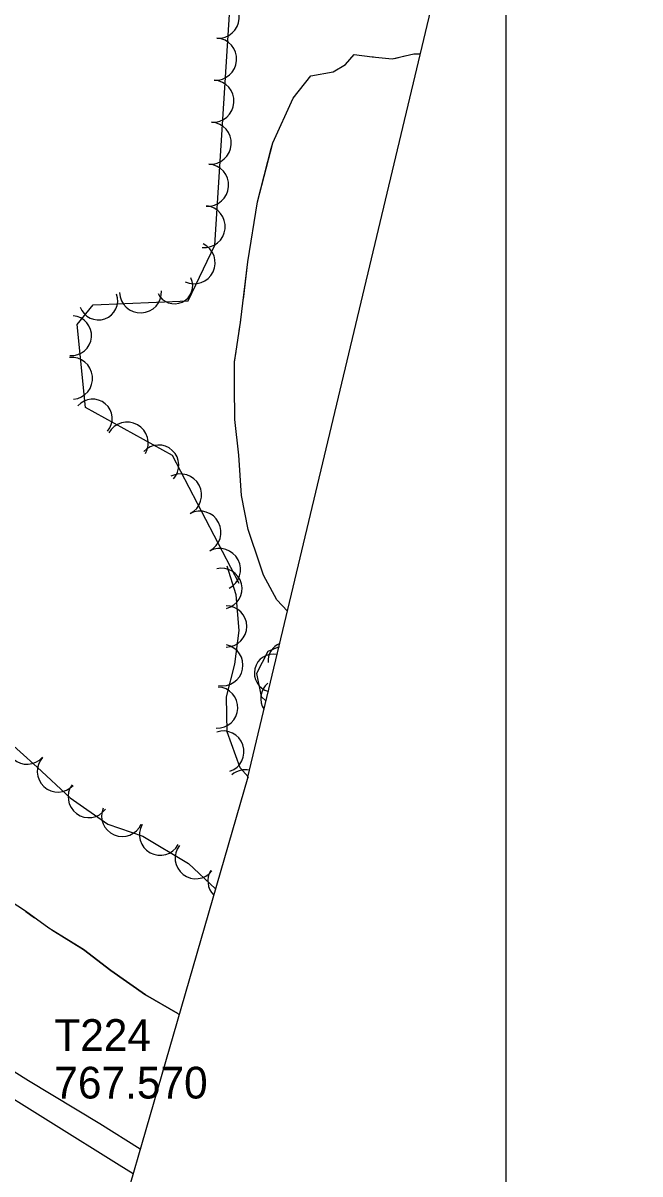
# Model space of a CAD drawing. Extents: x 591954 to 597000, y 198576 to 213500.
# Drawn here: x 596408.6 to 596525.3, y 204070.5 to 204288.1 of the extents above; entities that cross this region are included whole.
import ezdxf

# ---------------------------------------------------------------- set-up
doc = ezdxf.new("R2010")
doc.units = 0
for name, color, linetype in [('Level 10', 7, 'Continuous'), ('Level 11', 7, 'Continuous'), ('Level 18', 7, 'Continuous'), ('Level 19', 7, 'Continuous'), ('Level 4', 7, 'Continuous'), ('Level 5', 7, 'Continuous')]:
    doc.layers.add(name, color=color, linetype=linetype)

msp = doc.modelspace()

# ---------------------------------------------------------------- linework, layer by layer
at = {"layer": 'Level 10'}
for p, q in [((596500, 204000), (596500, 205500)), ((596500, 204000), (596500, 205500)), ((596500, 204000), (596500, 205500)), ((596500, 203500), (596500, 204500))]:
    msp.add_line(p, q, dxfattribs=at)
at = {"layer": 'Level 11'}
for points in [[(596429.44, 204070.52), (596426.81, 204072.19), (596413.87, 204080.23), (596400.87, 204088.31), (596389, 204095.58), (596377.25, 204102.78), (596364.91, 204110.13), (596352.62, 204117.51), (596341.53, 204124.08), (596329.34, 204131.2), (596316.86, 204138.42), (596305.16, 204145.16), (596290.94, 204153.27), (596277.68, 204160.85), (596266.03, 204167.49), (596254.43, 204174.01), (596246.04, 204178.87)], [(596430.78, 204075.17), (596423.12, 204079.95), (596409.67, 204088.08), (596395.51, 204096.91), (596377.37, 204107.84), (596359.1, 204118.92), (596339.87, 204130.04), (596322.37, 204140.72), (596307.82, 204149.24)]]:
    msp.add_lwpolyline(points, dxfattribs=at)
at = {"layer": 'Level 18'}
for points in [[(596449.49, 204182.14), (596436.86, 204206.32), (596420.41, 204215.43), (596418.86, 204231.12), (596421.86, 204234.86), (596439.83, 204235.58), (596444.88, 204246.14), (596448.48, 204302.69), (596477.13, 204303.31), (596488.73, 204303.07)], [(596449.49, 204182.14), (596436.86, 204206.32), (596420.41, 204215.43), (596418.86, 204231.12), (596421.86, 204234.86), (596439.83, 204235.58), (596444.88, 204246.14), (596448.48, 204302.69), (596477.13, 204303.31), (596488.73, 204303.07)], [(596449.49, 204182.14), (596436.86, 204206.32), (596420.41, 204215.43), (596418.86, 204231.12), (596421.86, 204234.86), (596439.83, 204235.58), (596444.88, 204246.14), (596448.48, 204302.69), (596477.13, 204303.31), (596488.73, 204303.07)], [(596451.16, 204145.58), (596449.68, 204147.31), (596447.19, 204154.08), (596447.1, 204160.73), (596448.68, 204166.91), (596449.45, 204173.29), (596448.88, 204180.01), (596447.2, 204185.4)], [(596349.72, 204182.23), (596354.79, 204180.08), (596364.73, 204175.11), (596375.76, 204169.42), (596387.49, 204163.2), (596396.9, 204157.48), (596404.83, 204153.22), (596411.29, 204147.43), (596417.54, 204141.65), (596424.63, 204136.66), (596431.29, 204134.37), (596439.92, 204129.2), (596445.03, 204124.39)], [(596457.03, 204170.2), (596454.91, 204169.28), (596452.78, 204165.11), (596453.65, 204160.77), (596454.57, 204159.87)], [(596451.24, 204145.49), (596451.23, 204145.5)]]:
    msp.add_lwpolyline(points, dxfattribs=at)
for centre, radius, start, end in [((596445.53, 204289.23), 3.98, 266.3698, 86.3545), ((596445.53, 204289.23), 3.98, 266.3698, 86.3545), ((596445.53, 204289.23), 3.98, 266.3698, 86.3545), ((596445.03, 204281.29), 3.98, 266.3703, 86.3549), ((596445.03, 204281.29), 3.98, 266.3703, 86.3549), ((596445.03, 204281.29), 3.98, 266.3703, 86.3549), ((596444.52, 204273.34), 3.98, 266.3626, 86.3473), ((596444.52, 204273.34), 3.98, 266.3626, 86.3473), ((596444.52, 204273.34), 3.98, 266.3626, 86.3473), ((596444.02, 204265.4), 3.98, 266.3703, 86.3549), ((596444.02, 204265.4), 3.98, 266.3703, 86.3549), ((596444.02, 204265.4), 3.98, 266.3703, 86.3549), ((596443.51, 204257.46), 3.98, 266.3698, 86.3545), ((596443.51, 204257.46), 3.98, 266.3698, 86.3545), ((596443.51, 204257.46), 3.98, 266.3698, 86.3545), ((596442.89, 204249.62), 3.96, 264.3864, 84.3711), ((596442.89, 204249.62), 3.96, 264.3864, 84.3711), ((596442.89, 204249.62), 3.96, 264.3864, 84.3711), ((596440.97, 204242.79), 3.98, 244.4567, 64.4414), ((596440.97, 204242.79), 3.98, 244.4567, 64.4414), ((596440.97, 204242.79), 3.98, 244.4567, 64.4414), ((596437.25, 204238.47), 3.44, 205.0698, 25.0545), ((596437.25, 204238.47), 3.44, 205.0698, 25.0545), ((596437.25, 204238.47), 3.44, 205.0698, 25.0545), ((596422.86, 204235.64), 3.65, 199.6018, 19.5865), ((596422.86, 204235.64), 3.65, 199.6018, 19.5865), ((596422.86, 204235.64), 3.65, 199.6018, 19.5865), ((596430.83, 204237.3), 3.98, 182.283, 2.2677), ((596430.83, 204237.3), 3.98, 182.283, 2.2677), ((596430.83, 204237.3), 3.98, 182.283, 2.2677), ((596417.79, 204229.02), 3.77, 265.4013, 85.386), ((596417.79, 204229.02), 3.77, 265.4013, 85.386), ((596417.79, 204229.02), 3.77, 265.4013, 85.386), ((596417.77, 204220.94), 3.98, 275.638, 95.6227), ((596417.77, 204220.94), 3.98, 275.638, 95.6227), ((596417.77, 204220.94), 3.98, 275.638, 95.6227), ((596421.79, 204213.34), 3.67, 319.6577, 139.6424), ((596421.79, 204213.34), 3.67, 319.6577, 139.6424), ((596421.79, 204213.34), 3.67, 319.6577, 139.6424), ((596428.31, 204208.68), 3.98, 331.0244, 151.009), ((596428.31, 204208.68), 3.98, 331.0244, 151.009), ((596428.31, 204208.68), 3.98, 331.0244, 151.009), ((596434.24, 204204.51), 3.82, 317.1901, 137.1747), ((596434.24, 204204.51), 3.82, 317.1901, 137.1747), ((596434.24, 204204.51), 3.82, 317.1901, 137.1747), ((596438.39, 204198.89), 3.98, 297.5707, 117.5554), ((596438.39, 204198.89), 3.98, 297.5707, 117.5554), ((596438.39, 204198.89), 3.98, 297.5707, 117.5554), ((596442.07, 204191.84), 3.98, 297.5771, 117.5618), ((596442.07, 204191.84), 3.98, 297.5771, 117.5618), ((596442.07, 204191.84), 3.98, 297.5771, 117.5618), ((596445.76, 204184.78), 3.98, 297.5674, 117.5521), ((596445.76, 204184.78), 3.98, 297.5674, 117.5521), ((596445.76, 204184.78), 3.98, 297.5674, 117.5521), ((596446.17, 204181.18), 3.85, 283.9934, 103.9781), ((596447.03, 204174.03), 3.89, 270.1107, 90.0954), ((596446.3, 204166.71), 3.9, 258.761, 78.7457), ((596458.55, 204167.49), 3.6, 112.3126, 184.2255), ((596455.96, 204165.2), 3.61, 78.6479, 254.7093), ((596445.33, 204158.69), 3.89, 267.3322, 87.3168), ((596457.27, 204160.42), 3.72, 129.7303, 214.2559), ((596409.38, 204151.89), 3.91, 138.1728, 318.1575), ((596446.49, 204150.37), 3.9, 288.5891, 108.5738), ((596415.19, 204146.61), 3.91, 137.3074, 317.2921), ((596450.66, 204143.03), 3.91, 78.205, 130.6635), ((596421.04, 204141.79), 3.91, 143.7388, 323.7235), ((596427.35, 204138.17), 3.88, 156.8633, 336.848), ((596434.52, 204134.66), 3.9, 150.9723, 330.957), ((596441.26, 204130.21), 3.89, 142.1818, 322.1664), ((596447.35, 204125.9), 3.79, 148.1955, 225.287)]:
    msp.add_arc(centre, radius, start, end, dxfattribs=at)
at = {"layer": 'Level 19'}
for points in [[(596453.45, 204185.6), (596451.17, 204192.33), (596449.92, 204198.77), (596449.39, 204206.39), (596448.69, 204213.13), (596448.59, 204219.5), (596448.57, 204224.02), (596449.71, 204231.47), (596451.14, 204242.97), (596452.96, 204254.31), (596455.83, 204265.49), (596459.66, 204273.93), (596463, 204278.12), (596467.27, 204278.9), (596469.6, 204280.28), (596471.22, 204282.2), (596474.62, 204281.76), (596478.43, 204281.34), (596482.5, 204282.29), (596483.77, 204282.28)], [(596453.45, 204185.6), (596451.17, 204192.33), (596449.92, 204198.77), (596449.39, 204206.39), (596448.69, 204213.13), (596448.59, 204219.5), (596448.57, 204224.02), (596449.71, 204231.47), (596451.14, 204242.97), (596452.96, 204254.31), (596455.83, 204265.49), (596459.66, 204273.93), (596463, 204278.12), (596467.27, 204278.9), (596469.6, 204280.28), (596471.22, 204282.2), (596474.62, 204281.76), (596478.43, 204281.34), (596482.5, 204282.29), (596483.77, 204282.28)], [(596453.45, 204185.6), (596451.17, 204192.33), (596449.92, 204198.77), (596449.39, 204206.39), (596448.69, 204213.13), (596448.59, 204219.5), (596448.57, 204224.02), (596449.71, 204231.47), (596451.14, 204242.97), (596452.96, 204254.31), (596455.83, 204265.49), (596459.66, 204273.93), (596463, 204278.12), (596467.27, 204278.9), (596469.6, 204280.28), (596471.22, 204282.2), (596474.62, 204281.76), (596478.43, 204281.34), (596482.5, 204282.29), (596483.77, 204282.28)], [(596455.55, 204264.4), (596455.83, 204265.49), (596459.66, 204273.93), (596463, 204278.12), (596467.27, 204278.9), (596469.6, 204280.28), (596471.22, 204282.2), (596474.62, 204281.76), (596474.87, 204281.73)], [(596478.84, 204281.44), (596480.79, 204281.89)], [(596450.27, 204235.93), (596451.14, 204242.97), (596452.96, 204254.31), (596455.55, 204264.4)], [(596449.49, 204229.98), (596449.71, 204231.47), (596449.78, 204231.96)], [(596448.58, 204224.05), (596448.88, 204226.02)], [(596448.61, 204218.05), (596448.59, 204219.5), (596448.59, 204220.05)], [(596453.45, 204185.6), (596451.17, 204192.33), (596449.92, 204198.77), (596449.39, 204206.39), (596448.69, 204213.13), (596448.67, 204214.05)], [(596458.63, 204176.89), (596456.63, 204179.09), (596454.09, 204183.7), (596453.45, 204185.6)], [(596438.15, 204100.61), (596437.86, 204100.83), (596431.79, 204104.4), (596425.22, 204108.95), (596420.02, 204112.96), (596413.51, 204117), (596409.05, 204120.19), (596400.32, 204125.85), (596392.99, 204130.53), (596385.51, 204134.93), (596377.69, 204138.72), (596369.93, 204142.59), (596362.99, 204146.29), (596355.28, 204150.39), (596346.34, 204155.41), (596338.49, 204160.51), (596329.85, 204165.63), (596321.63, 204170.55), (596316.26, 204173.43), (596310.85, 204176.19)], [(596409.14, 204120.13), (596410.76, 204118.96)], [(596414.04, 204116.67), (596420.02, 204112.96), (596425.22, 204108.95), (596431.79, 204104.4), (596437.86, 204100.83), (596438.15, 204100.61)]]:
    msp.add_lwpolyline(points, dxfattribs=at)
at = {"layer": 'Level 4'}
for points in [[(596451.14, 204145.51), (596525.27, 204456.26), (596301.7, 204553.02), (596061.01, 204676.82), (595803.6, 204793.01), (595657.91, 204869.81), (595496.03, 204962.18), (595284.73, 205098.89)], [(596451.14, 204145.51), (596525.27, 204456.26), (596301.7, 204553.02), (596061.01, 204676.82), (595803.6, 204793.01), (595657.91, 204869.81), (595496.03, 204962.18), (595284.73, 205098.89)], [(596451.14, 204145.51), (596525.27, 204456.26), (596301.7, 204553.02), (596061.01, 204676.82), (595803.6, 204793.01), (595657.91, 204869.81), (595496.03, 204962.18), (595284.73, 205098.89)], [(596451.14, 204145.51), (596324.17, 203706.85)]]:
    msp.add_lwpolyline(points, dxfattribs=at)

# ---------------------------------------------------------------- texts
at = {"layer": 'Level 5'}
for s, p in [('T224', (596414.52, 204093.77)), ('T224', (596414.52, 204093.77)), ('T224', (596414.52, 204093.77)), ('T224', (596414.52, 204093.77)), ('767.570', (596414.52, 204084.77)), ('767.570', (596414.52, 204084.77)), ('767.570', (596414.52, 204084.77)), ('767.570', (596414.52, 204084.77))]:
    msp.add_text(s, height=6, dxfattribs=at).set_placement(p)

doc.saveas('drawing.dxf')
